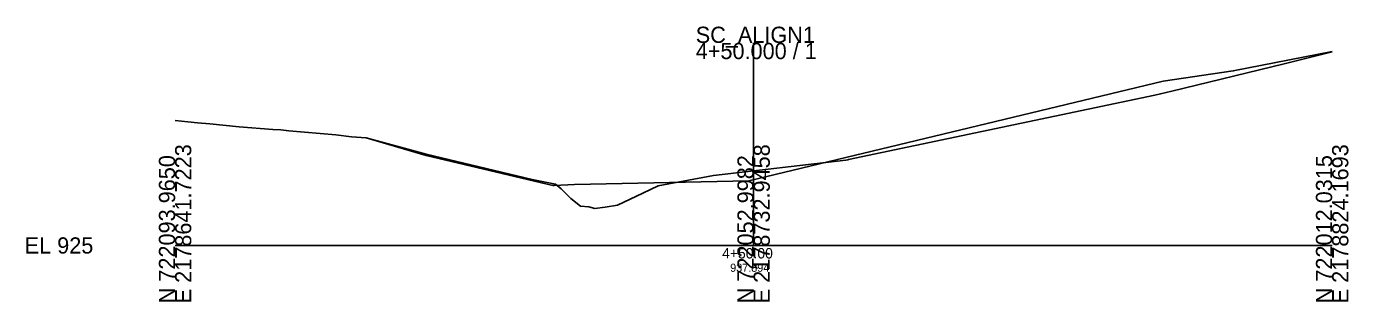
# Model space of a CAD drawing. Extents: x -2342 to 14913, y -10 to 5257.
# Drawn here: x 974.3 to 1202.8, y 3990.3 to 4037.8 of the extents above; entities that cross this region are included whole.
import ezdxf

# ---------------------------------------------------------------- set-up
doc = ezdxf.new("R2010")
doc.units = 0
for name, color, linetype in [('Default', 7, 'Continuous'), ('GK_Cells', 7, 'Continuous'), ('SC_Scratch1', 7, 'Continuous'), ('XS_P_Annotation', 7, 'Continuous'), ('XS_X_Ground_Line', 7, 'Continuous')]:
    doc.layers.add(name, color=color, linetype=linetype)

msp = doc.modelspace()

# ---------------------------------------------------------------- linework, layer by layer
at = {"layer": 'GK_Cells'}
for p, q in [((1100, 4000), (1100, 4035)), ((1000, 4000), (1100, 4000)), ((1100, 4000), (1200, 4000))]:
    msp.add_line(p, q, dxfattribs=at)
at = {"layer": 'SC_Scratch1'}
msp.add_lwpolyline([(1000, 4021.58), (1002.23, 4021.36), (1003.9, 4021.2), (1006.01, 4021.01), (1011.09, 4020.5), (1016.88, 4020.05), (1018.29, 4019.95), (1019.68, 4019.82), (1027.76, 4019.12), (1030.48, 4018.74), (1033.04, 4018.61), (1043.39, 4015.56), (1065.32, 4010.37), (1065.43, 4010.35), (1065.52, 4010.35), (1069.03, 4010.54), (1099.15, 4011.17), (1170.8, 4028.36), (1182.91, 4030.17), (1200, 4033.49)], dxfattribs=at)
at = {"layer": 'XS_X_Ground_Line'}
msp.add_lwpolyline([(1000, 4021.58), (1002.23, 4021.36), (1003.9, 4021.2), (1006.01, 4021.01), (1011.09, 4020.5), (1016.88, 4020.05), (1018.29, 4019.95), (1019.68, 4019.82), (1027.76, 4019.12), (1030.48, 4018.74), (1033.04, 4018.61), (1043.39, 4015.76), (1061.73, 4011.38), (1065.73, 4010.6), (1066.75, 4009.77), (1068.39, 4008.1), (1070.09, 4006.79), (1071.51, 4006.69), (1072.57, 4006.37), (1074.36, 4006.62), (1076.46, 4006.94), (1080.84, 4009.06), (1083.49, 4010.32), (1093.09, 4012.09), (1115.97, 4014.75), (1116.21, 4014.78), (1116.31, 4014.79), (1116.42, 4014.83), (1169.37, 4025.97), (1172.3, 4026.66), (1191.69, 4031.39), (1200, 4033.45)], dxfattribs=at)

# ---------------------------------------------------------------- texts
at = {"layer": 'Default'}
msp.add_text('-', height=0.0001, dxfattribs=at).set_placement((1000, 4000))
at = {"layer": 'GK_Cells'}
for s, p in [('SC_ALIGN1', (1090, 4035)), ('4+50.000 / 1', (1090, 4032.2)), ('EL 925', (974, 3998.6))]:
    msp.add_text(s, height=2.8, dxfattribs=at).set_placement(p)
for s, p in [('N 722093.9650', (1000, 3990)), ('E 2178641.7223', (1002.8, 3990)), ('N 722052.9982', (1100, 3990)), ('E 2178732.9458', (1102.8, 3990)), ('N 722012.0315', (1200, 3990)), ('E 2178824.1693', (1202.8, 3990))]:
    msp.add_text(s, height=2.8, rotation=90, dxfattribs=at).set_placement(p)
at = {"layer": 'SC_Scratch1'}
msp.add_text('X', height=0.0001, dxfattribs=at).set_placement((1100, 4012.89))
at = {"layer": 'XS_P_Annotation'}
for s, height, p in [('4+50.00', 1.8, (1094.56, 3997.75)), ('937.894', 1.4, (1095.95, 3995.45))]:
    msp.add_text(s, height=height, dxfattribs=at).set_placement(p)

doc.saveas('drawing.dxf')
